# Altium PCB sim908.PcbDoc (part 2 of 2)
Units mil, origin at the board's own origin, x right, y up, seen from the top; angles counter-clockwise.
Board outline 6000 x 4000 mil, 2 copper layers (Top Layer, Bottom Layer); 77 components, 69 nets, 376 pads, 43 vias.
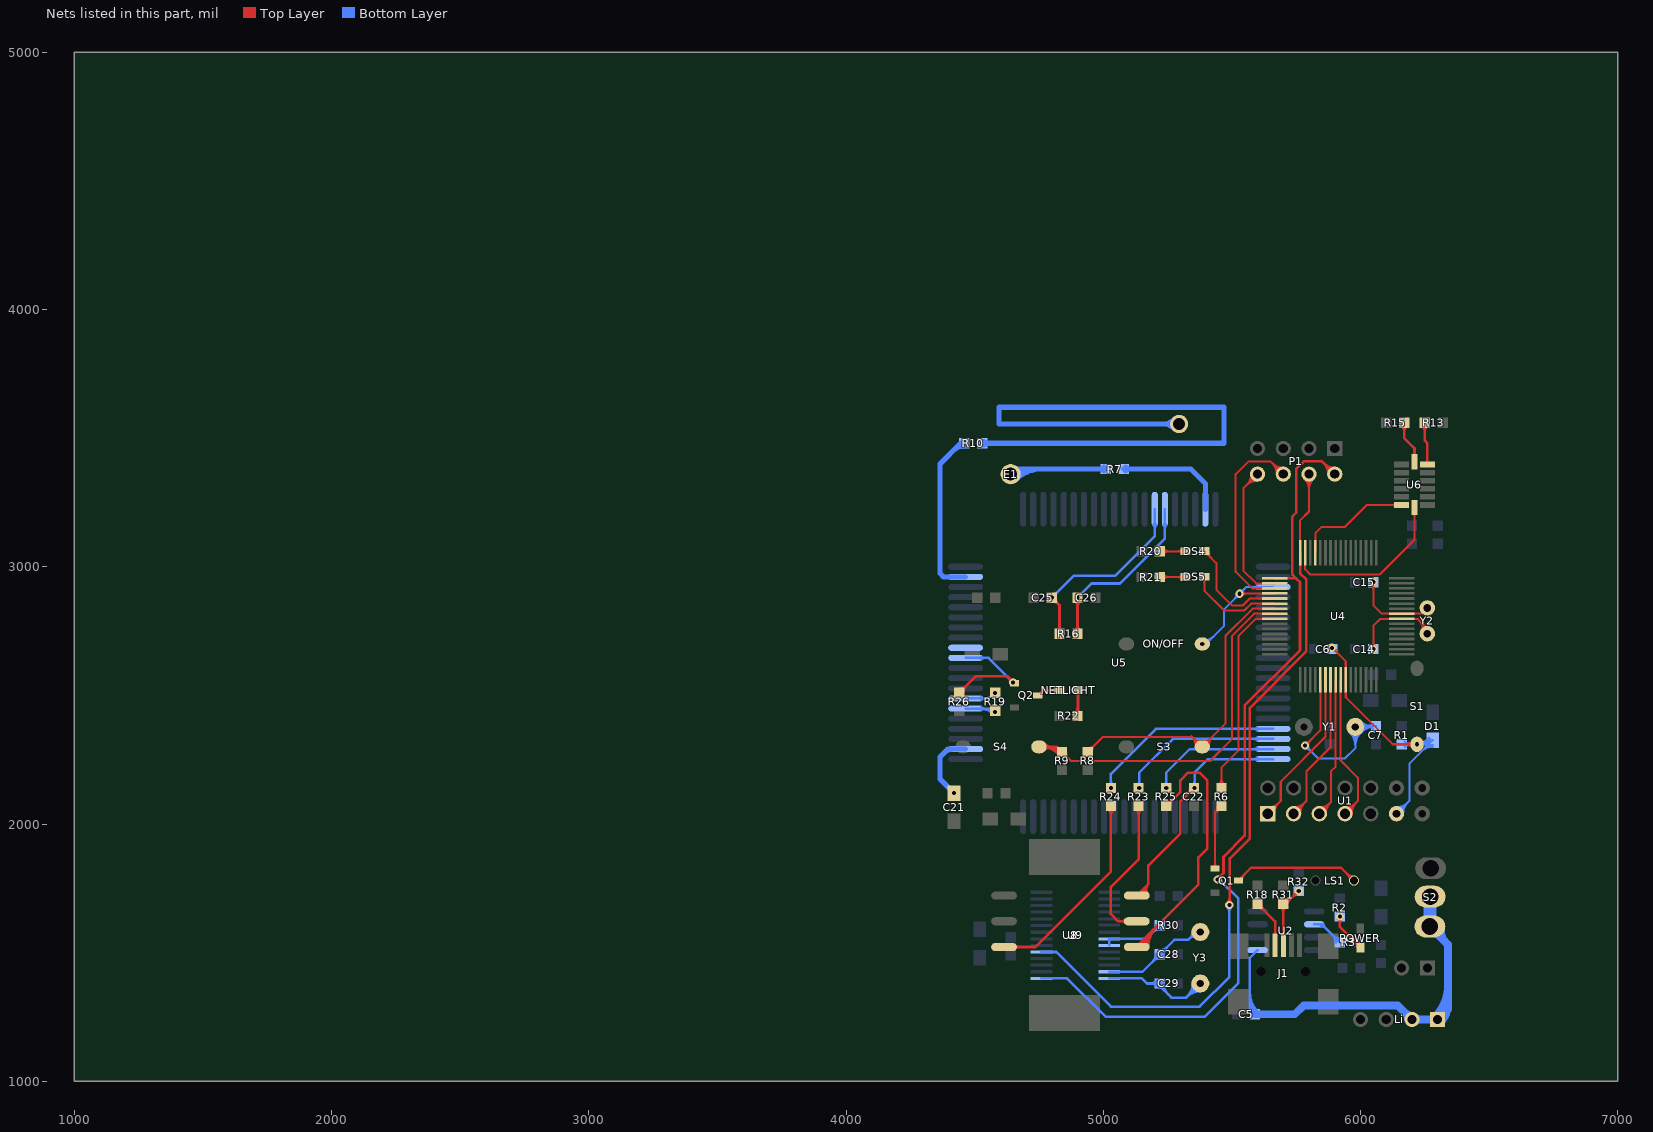
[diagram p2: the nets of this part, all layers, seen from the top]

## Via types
v1: diameter 31.5, hole 15.75, Top Layer to Bottom Layer, 41 vias
v2: diameter 39.37, hole 19.68, Top Layer to Bottom Layer, 2 vias

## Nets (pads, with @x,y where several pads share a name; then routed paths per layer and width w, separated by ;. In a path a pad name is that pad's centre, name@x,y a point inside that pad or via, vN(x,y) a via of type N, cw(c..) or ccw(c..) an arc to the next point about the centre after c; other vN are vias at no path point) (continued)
NetC7_2: C7.2 U4.53 Y1.1 | length 1325.3
  Top Layer w8: v1(5785,2305) 5844.25,2364.25 U4.53@5844.25,2560.79 ; v1@5785,2316.75 ccw(c5785,2345.11) 5805.06,2325.06 ccw(c5825.11,2305) v1@5796.75,2305
  Bottom Layer w8: v1@5785,2293.25 cw(c5785,2264.89) 5805.06,2284.94 cw(c5825.11,2305) v1@5796.75,2305 ; v1(5785,2305) 5835,2255 5940,2255 5979.92,2294.92 Y1.1@5979.92,2377.48 5982.44,2380 C7.2@6060,2380 ccw(c6060,2298.59) Y1.1@6002,2355.72 ; Y1.1@5958,2355.56 cw(c5905.08,2302.64) 5979.92,2302.64 cw(c6054.76,2302.64) Y1.1@6001.84,2355.56 ; Y1.1@5963.66,2361.22 cw(c5924.39,2321.95) 5979.92,2321.95 cw(c6035.45,2321.95) Y1.1@5996.18,2361.22 ; Y1.1@5969.31,2366.87 cw(c5943.71,2341.27) 5979.92,2341.27 cw(c6016.13,2341.27) Y1.1@5990.53,2366.87 ; Y1.1@5990.61,2366.95 cw(c6021.77,2336.25) 6021.77,2380 ; Y1.1@5996.18,2393.74 ccw(c6029.36,2426.92) 6029.36,2380 ; Y1.1@5996.31,2361.34 cw(c6040.89,2317.42) C7.2@6040.89,2380 ; Y1.1@6001.84,2399.4 ccw(c6048.68,2446.24) C7.2@6048.68,2380 ; C7.2@6048.69,2368.69 ccw(c6021.37,2341.37) 6021.37,2380 ccw(c6021.37,2418.63) C7.2@6048.69,2391.31
NetC14_2: C14.2 U4.8 Y2.2 | length 540.8
  Top Layer w8: v1@6041.69,2688.31 ccw(c6021.64,2708.36) 6050,2708.36 ccw(c6078.36,2708.36) v1@6058.31,2688.31 ; v1@6050,2685 6050,2770 6077.8,2797.8 U4.8@6160,2797.8 6222.2,2797.8 6260,2760 Y2.2@6260,2740 ; 6223.73,2796.27 cw(c6177.98,2750.53) Y2.2@6242.15,2742.29 ; 6235.24,2784.76 cw(c6198.39,2747.91) Y2.2@6250.08,2741.27 ; 6246.76,2773.24 cw(c6218.81,2745.29) Y2.2@6258.02,2740.25 ; 6249.76,2770.24 ccw(c6260,2780.49) Y2.2@6260,2766
  other v1: 6050,2680
NetC15_2: C15.2 U4.9 Y2.1 | length 367.4
  Top Layer w8: v1@6041.69,2931.69 cw(c6021.64,2911.64) 6050,2911.64 cw(c6078.36,2911.64) v1@6058.31,2931.69 ; v1(6050,2940) 6050,2849.96 6082.48,2817.48 U4.9@6160,2817.48 6237.48,2817.48 Y2.1@6260,2840
NetC25_1: C25.1 R16.2 U5.74 | length 976.7
  Top Layer w10: C25.1@4800,2865 cw(c4800,2828.79) 4825.61,2854.39 cw(c4851.21,2880) C25.1@4815,2880 ; C25.1@4800,2869.25 cw(c4800,2843.3) 4818.35,2861.65 cw(c4836.7,2880) C25.1@4810.75,2880 ; v1(4800,2880) 4830,2850 R16.2@4830,2740 ; R16.2@4819.39,2750.61 ccw(c4793.79,2776.21) 4830,2776.21 ccw(c4866.21,2776.21) R16.2@4840.61,2750.61
  Bottom Layer w10: v1(4800,2880) 4885,2965 5045.35,2965 5200.35,3120 U5.74@5200.35,3223.43 ; v1@4800,2890.75 ccw(c4800,2916.7) 4818.35,2898.35 ccw(c4836.7,2880) v1@4810.75,2880 ; U5.74@5195.54,3162.51 cw(c5183.91,3150.88) 5200.35,3150.88 cw(c5216.8,3150.88) U5.74@5205.17,3162.51
NetC26_1: C26.1 R16.1 U5.75 | length 909.5
  Top Layer w10: R16.1@4889.39,2750.61 ccw(c4863.79,2776.21) 4900,2776.21 ccw(c4936.21,2776.21) R16.1@4910.61,2750.61 ; C26.1@4889.39,2869.39 cw(c4863.79,2843.79) 4900,2843.79 cw(c4936.21,2843.79) C26.1@4910.61,2869.39 ; C26.1@4892.4,2872.4 cw(c4874.05,2854.05) 4900,2854.05 cw(c4925.95,2854.05) C26.1@4907.6,2872.4 ; R16.1@4900,2740 v1(4900,2880)
  Bottom Layer w10: v1(4900,2880) 4955,2935 5064.72,2935 5239.72,3110 U5.75@5239.72,3223.43 ; v1@4900,2890.75 ccw(c4900,2916.7) 4918.35,2898.35 ccw(c4936.7,2880) v1@4910.75,2880 ; U5.75@5234.91,3162.51 cw(c5223.28,3150.88) 5239.72,3150.88 cw(c5256.17,3150.88) U5.75@5244.54,3162.51
NetC28_1: C28.1 U9.27 Y3.2 | length 629.7
  Bottom Layer w10: U9.27@5023.78,1425.59 5152.26,1425.59 C28.1@5220,1493.33 5276.67,1550 5330,1550 5360.08,1580.08 Y3.2@5377.48,1580.08 ; C28.1@5205,1493.33 cw(c5168.79,1493.33) 5194.39,1467.73 cw(c5220,1442.12) C28.1@5220,1478.33 ; C28.1@5220,1508.33 ccw(c5220,1544.55) 5245.61,1518.94 ccw(c5271.21,1493.33) C28.1@5235,1493.33 ; 5332.52,1552.52 cw(c5358.58,1526.47) Y3.2@5370.83,1561.22 ; 5338.57,1558.57 ccw(c5317.07,1580.08) Y3.2@5347.48,1580.08 ; 5343.75,1563.75 cw(c5364.43,1543.07) Y3.2@5374.15,1570.65
NetC29_1: C29.1 U9.28 Y3.1 | length 755.3
  Bottom Layer w10: U9.28@5023.78,1400 5150,1400 5170,1380 C29.1@5220,1380 ; C29.1@5209.39,1369.39 ccw(c5183.79,1343.79) 5183.79,1380 ccw(c5183.79,1416.21) C29.1@5209.39,1390.61 ; C29.1@5220,1365 cw(c5220,1352.93) C29.1@5228.54,1361.46 ; C29.1@5220,1390 C29.1@5220,1380 ; C29.1@5225,1380 ccw(c5261.21,1380) 5235.61,1354.39 ; C29.1@5235,1380 ccw(c5295.36,1380) 5252.68,1337.32 ; Y3.1@5347.48,1380.08 cw(c5275.05,1380.08) 5326.27,1328.87 cw(c5377.48,1277.65) Y3.1@5377.48,1350.08 ; Y3.1@5357.48,1380.08 cw(c5309.2,1380.08) 5343.34,1345.94 cw(c5377.48,1311.79) Y3.1@5377.48,1360.08 ; Y3.1@5377.48,1380.08 5322.4,1325 5265,1325 5220,1370 C29.1@5220,1380
NetDS1_2: POWER.2 R2.1 | length 231.8
  Top Layer w10: v1@5912.4,1632.4 cw(c5894.05,1614.05) 5920,1614.05 cw(c5945.95,1614.05) v1@5927.6,1632.4 ; v1(5920,1640) 5920,1600 POWER.2@6000,1520 ; 5974.39,1545.61 ccw(c6000,1571.21) POWER.2@6000,1535 ; POWER.2@5986.46,1533.54 cw(c5977.93,1525) POWER.2@5990,1525
NetDS4_2: DS4.2 R20.1 | length 202.4
  Top Layer w8: R20.1@5220,3060 DS4.2@5320,3060 ; R20.1@5231.31,3048.69 cw(c5258.63,3021.37) 5258.63,3060 cw(c5258.63,3098.63) R20.1@5231.31,3071.31 ; DS4.2@5307.22,3052.22 ccw(c5288.44,3033.44) 5288.44,3060 ccw(c5288.44,3086.56) DS4.2@5307.22,3067.78
NetDS5_2: DS5.2 R21.1 | length 202.4
  Top Layer w8: R21.1@5220,2960 DS5.2@5320,2960 ; R21.1@5231.31,2948.69 cw(c5258.63,2921.37) 5258.63,2960 cw(c5258.63,2998.63) R21.1@5231.31,2971.31 ; DS5.2@5307.22,2952.22 ccw(c5288.44,2933.44) 5288.44,2960 ccw(c5288.44,2986.56) DS5.2@5307.22,2967.78
NetDS6_1: NETLIGHT.1 R22.1 | length 196.6
  Top Layer w10: R22.1@4889.39,2430.61 ccw(c4859.13,2460.87) 4901.93,2460.87 ; NETLIGHT.1@4894.86,2513.93 cw(c4877.79,2496.86) 4901.93,2496.86 cw(c4926.07,2496.86) NETLIGHT.1@4909,2513.93 ; R22.1@4900,2420 4901.93,2421.93 NETLIGHT.1@4901.93,2521 ; 4901.93,2451.56 ccw(c4931.56,2451.56) R22.1@4910.61,2430.61
NetDS6_2: NETLIGHT.2 Q2.3 | length 151.4
  Top Layer w10: Q2.3@4745.28,2500 4765.27,2520 ; Q2.3@4757.98,2500.48 cw(c4783.04,2502.23) 4765.27,2520 ; NETLIGHT.2@4816.93,2512.93 ccw(c4799.86,2495.86) 4799.86,2520 ccw(c4799.86,2544.14) NETLIGHT.2@4816.93,2527.07 ; NETLIGHT.2@4829,2520 4765.27,2520
NetE1_1: E1.1 R7.2 | length 596.9
  Bottom Layer w20: E1.1@4640,3360 4660,3380 R7.2@5010,3380 ; E1.1@4646.63,3353.37 cw(c4710.91,3289.09) 4710.91,3380 ; E1.1@4660.77,3339.23 cw(c4759.19,3240.81) 4759.19,3380 ; R7.2@5002.93,3372.93 ccw(c4985.86,3355.86) 4985.86,3380 ccw(c4985.86,3404.14) R7.2@5002.93,3387.07
NetE2_1: pad.1 R10.2 | length 2854.4
  Bottom Layer w20: R10.2@4530,3480 5470,3480 5470,3620 4595,3620 4595,3555 pad.1@5295,3555 ; R10.2@4537.07,3472.93 cw(c4554.14,3455.86) 4554.14,3480 cw(c4554.14,3504.14) R10.2@4537.07,3487.07 ; pad.1@5277.02,3537.02 ccw(c5233.6,3493.6) 5233.6,3555 ccw(c5233.6,3616.4) pad.1@5277.02,3572.98
NetJ1_2: J1.2 R18.2 | length 264.6
  Top Layer w10: R18.2@5600,1675 cw(c5600,1638.79) 5625.61,1664.39 cw(c5651.21,1690) R18.2@5615,1690 ; R18.2@5600,1690 5668.5,1621.5 J1.2@5668.5,1529.06 ; J1.2@5665.08,1567.91 ccw(c5656.81,1576.18) 5668.5,1576.18 ccw(c5680.19,1576.18) J1.2@5671.93,1567.91
NetJ1_3: J1.3 R31.2 R32.1 | length 443
  Top Layer w10: R31.2@5689.39,1679.39 cw(c5663.79,1653.79) 5700,1653.79 cw(c5736.22,1653.78) R31.2@5710.61,1679.39 ; J1.3@5696.57,1567.91 ccw(c5688.31,1576.18) 5700,1576.18 ccw(c5711.69,1576.18) J1.3@5703.42,1567.91 ; J1.3@5700,1529.06 R31.2@5700,1690 5710,1690 v1(5760,1740) ; R31.2@5700,1695 ccw(c5700,1731.21) 5725.61,1705.61 ; R31.2@5700,1705 ccw(c5700,1765.36) 5742.68,1722.68 ; R31.2@5715,1690 cw(c5727.07,1690) R31.2@5718.54,1698.54 ; v1@5749.25,1740 cw(c5723.3,1740) 5741.65,1721.65 cw(c5760,1703.3) v1@5760,1729.25
NETLIGHT: Q2.1 R26.2 U5.51 | length 666
  Top Layer w10: R26.2@4440,2510 4505,2575 4626.97,2575 Q2.1@4654.72,2547.24 ; R26.2@4440,2525 ccw(c4440,2561.21) 4465.61,2535.61 ccw(c4491.21,2510) R26.2@4455,2510 ; 4630.26,2571.71 cw(c4608.55,2550) Q2.1@4639.25,2550 ; 4633.02,2568.95 cw(c4611.31,2547.24) Q2.1@4642.01,2547.24 ; 4635.01,2566.96 ccw(c4650,2581.94) v1@4650,2560.75
  Bottom Layer w10: U5.51@4465.12,2645.67 4554.33,2645.67 v1(4650,2550) ; U5.51@4526.04,2640.85 cw(c4537.66,2629.23) 4537.66,2645.67 cw(c4537.66,2662.11) U5.51@4526.04,2650.49 ; v1@4639.25,2550 ccw(c4613.3,2550) 4631.65,2568.35 ccw(c4650,2586.7) v1@4650,2560.75
NetLS1_2: LS1.2 Q1.3 | length 570.9
  Top Layer w10: Q1.3@5525.28,1780 5575.18,1829.9 5925.1,1829.9 LS1.2@5975,1780 ; Q1.3@5537.99,1780 cw(c5568.69,1780) 5546.98,1801.71 ; 5949.6,1805.41 cw(c5924.19,1780) LS1.2@5960.12,1780 ; 5950.07,1804.93 ccw(c5974.8,1829.66) LS1.2@5974.8,1794.68
NetQ1_1: Q1.1 R6.1 | length 336.6
  Top Layer w8: Q1.1@5429.2,1832.77 ccw(c5415.87,1846.1) 5434.72,1846.1 ccw(c5453.58,1846.1) Q1.1@5440.25,1832.77 ; Q1.1@5434.72,1827.24 5434.72,1880 5434.72,2044.72 R6.1@5460,2070 ; R6.1@5444.03,2069.1 cw(c5412.15,2067.3) 5434.73,2044.73 cw(c5457.3,2022.15) R6.1@5459.1,2054.03
NetR3_1: R3.1 U2.2 | length 212.4
  Bottom Layer w10: U2.2@5820,1610 5850,1610 R3.1@5920,1540 ; U2.2@5848,1603 cw(c5848,1581.27) 5863.36,1596.64 ; U2.2@5855,1610 ccw(c5867.07,1610) 5858.54,1601.46 ; R3.1@5905,1540 ccw(c5868.79,1540) 5894.39,1565.61 ccw(c5920,1591.21) R3.1@5920,1555
NetR7_1: R7.1 U5.79 | length 478.2
  Bottom Layer w20: R7.1@5080,3380 5340,3380 5397.2,3322.8 U5.79@5397.2,3223.43 ; R7.1@5087.07,3372.93 cw(c5104.14,3355.86) 5104.14,3380 cw(c5104.14,3404.14) R7.1@5087.07,3387.07
NetR10_1: R10.1 U5.59 | length 706.6
  Bottom Layer w20: 4417.32,3452.32 cw(c4460,3409.64) R10.1@4460,3470 ; R10.1@4460,3480 4445,3480 4365,3400 4365,2975 4379.37,2960.63 U5.59@4465.12,2960.63
NetR13_2: R13.2 U6.6 | length 245.6
  Top Layer w10: R13.2@6239.39,3549.39 cw(c6213.79,3523.79) 6250,3523.79 cw(c6286.21,3523.79) R13.2@6260.61,3549.39 ; R13.2@6250,3560 6250,3490 6260,3480 U6.6@6260,3397.5 ; U6.6@6255.88,3401.62 ccw(c6245.93,3411.57) 6260,3411.57 ccw(c6274.07,3411.57) U6.6@6264.12,3401.62
NetR15_2: R15.2 U6.7 | length 247.5
  Top Layer w10: R15.2@6159.39,3549.39 cw(c6133.79,3523.79) 6170,3523.79 cw(c6206.21,3523.79) R15.2@6180.61,3549.39 ; R15.2@6170,3560 6170,3500 6210,3460 U6.7@6210,3408 ; U6.7@6205.88,3430.82 ccw(c6195.93,3440.77) 6210,3440.77 ccw(c6224.07,3440.77) U6.7@6214.12,3430.82
NetR17_1: 
NetR19_1: R19.1 U5.46 | length 261.9
  Bottom Layer w10: U5.46@4465.12,2448.82 4566.18,2448.82 v1(4580,2435) ; U5.46@4520.69,2448.82 cw(c4520.69,2375.69) v1@4572.4,2427.4 ; U5.46@4526.04,2444 cw(c4537.66,2432.38) 4537.66,2448.82 cw(c4537.66,2465.26) U5.46@4526.04,2453.64 ; 4544.83,2448.82 cw(c4544.83,2399.83) v1@4579.47,2434.47 ; 4568.97,2448.82 cw(c4568.97,2423.97) v1@4586.54,2441.54
NetR19_2: R19.2 U5.47 | length 185.5
  Bottom Layer w10: U5.47@4465.12,2488.19 4553.19,2488.19 v1@4575,2510 ; U5.47@4526.04,2483.37 cw(c4537.66,2471.75) 4537.66,2488.19 cw(c4537.66,2504.63) U5.47@4526.04,2493.01 ; 4553.12,2488.12 cw(c4580,2461.23) v1@4580,2499.25 ; 4565.19,2500.19 ccw(c4555.38,2510) v1@4569.25,2510
  other v1: 4580,2510
NetR29_1: 
NetR30_2: R30.2 U9.22 U9.23 | length 300.7
  Bottom Layer w10: U9.23@5023.78,1527.95 U9.22@5023.78,1553.54 5166.88,1553.54 R30.2@5220,1606.67 ; R30.2@5205,1606.67 cw(c5168.79,1606.67) 5194.39,1581.06 cw(c5220,1555.45) R30.2@5220,1591.67
P4.0: ON/OFF.2 U4.36 U5.3 | length 813.9
  Top Layer w8: v1@5531.22,2896.22 U4.36@5666.3,2896.22 ; v1@5538.31,2886.69 cw(c5561.31,2863.69) 5561.31,2896.22 ; v1@5538.31,2903.31 ccw(c5555.42,2920.42) 5555.42,2896.22
  Bottom Layer w8: v1@5385,2695.75 ccw(c5385,2721.7) 5403.35,2703.35 ; v1(5385,2700) 5390,2695 5395,2695 5470,2770 5470,2835 5556.26,2921.26 U5.3@5660,2921.26 ; v1@5385,2703.75 ccw(c5385,2749.01) 5417,2717 ; v1@5385,2711.75 ccw(c5385,2776.32) 5430.66,2730.66 ; v1@5518.25,2895 cw(c5489.89,2895) 5509.94,2874.94 cw(c5530,2854.89) v1@5530,2883.25 ; v1@5530,2906.75 ccw(c5530,2935.11) 5550.06,2915.06 ccw(c5570.11,2895) v1@5541.75,2895 ; U5.3@5598.37,2915.74 ccw(c5585.04,2902.4) 5585.04,2921.26 ccw(c5585.04,2940.12) U5.3@5598.37,2926.78
  other v1: 5530,2895
P4.1: DS4.1 U4.37 | length 489.5
  Top Layer w8: DS4.1@5392.93,3061 5440,3013.93 5440,2910 5500,2850 5543.18,2850 5569.71,2876.53 U4.37@5666.3,2876.53 ; DS4.1@5397.93,3050 cw(c5397.93,3035.51) 5408.17,3045.76 ; DS4.1@5400.93,3061 ccw(c5420.24,3061) DS4.1@5406.58,3047.34 ; DS4.1@5408.93,3061 ccw(c5447.56,3061) 5420.24,3033.69
P4.2: DS5.1 U4.38 | length 412.1
  Top Layer w8: DS5.1@5385.15,2953.22 cw(c5366.37,2934.44) 5392.93,2934.44 cw(c5419.48,2934.44) DS5.1@5400.71,2953.22 ; DS5.1@5392.93,2961 5392.93,2907.07 5470,2830 5548.63,2830 5575.48,2856.85 U4.38@5666.3,2856.85
P4.3: R8.1 S3.1 U4.39 | length 1469.5
  Top Layer w8: R8.1@4940,2280 4999,2339 5346,2339 S3.1@5385,2300 5475,2390 5475,2730.91 5581.25,2837.16 U4.39@5666.3,2837.16 ; R8.1@4940,2296 ccw(c4940,2334.63) 4967.31,2307.31 ccw(c4994.63,2280) R8.1@4956,2280 ; 5343.5,2341.5 cw(c5305.85,2303.84) S3.1@5359.03,2301.09 ; 5352.69,2332.31 ccw(c5380,2359.63) S3.1@5380,2321 ; 5356.22,2328.78 cw(c5330.02,2302.59) S3.1@5367.02,2300.67 ; S3.1@5390,2321 ccw(c5390,2359.63) 5417.31,2332.31 ; S3.1@5403,2300 cw(c5446.46,2300) 5415.73,2330.73 ; S3.1@5411,2300 cw(c5473.77,2300) 5429.38,2344.38
P4.4: R9.1 S4.1 U4.40 | length 1736.6
  Top Layer w8: R9.1@4840,2264 cw(c4840,2225.37) 4867.31,2252.69 cw(c4894.63,2280) R9.1@4856,2280 ; R9.1@4840,2280 4875,2245 5415,2245 5500,2330 5500,2730.46 5587.02,2817.48 U4.40@5666.3,2817.48
  Top Layer w10: S4.1@4750,2300 4820,2300 R9.1@4840,2280 ; S4.1@4755.5,2300 cw(c4755.5,2195.5) R9.1@4829.39,2269.39 ; S4.1@4769.14,2285.86 cw(c4803.28,2251.72) 4803.28,2300 cw(c4803.28,2348.28) S4.1@4769.14,2314.14 ; S4.1@4779.64,2300 cw(c4779.64,2219.64) R9.1@4836.46,2276.46 ; 4803.79,2300 cw(c4803.79,2243.79) R9.1@4843.54,2283.54
P4.5: R6.2 U4.41 | length 847
  Top Layer w8: R6.2@5448.69,2151.31 ccw(c5421.37,2178.63) 5460,2178.63 ccw(c5498.63,2178.63) R6.2@5471.31,2151.31 ; R6.2@5460,2140 5460,2220 5525,2285 5525,2730 5592.8,2797.8 U4.41@5666.3,2797.8
POWER: C5.2 Li.1 Li.2 S2.1 S2.2 U2.5 | length 2255.5
  Bottom Layer w10: 5570,1296.21 ccw(c5626.21,1296.21) C5.2@5586.46,1256.46 ; 5570,1320.36 ccw(c5650.36,1320.36) C5.2@5593.54,1263.54 ; 5570,1344.5 ccw(c5674.5,1344.5) C5.2@5600.61,1270.61 ; C5.2@5590,1260 5570,1280 5570,1480 U2.5@5600,1510
  Bottom Layer w30: C5.2@5590,1260 5745,1260 5779.53,1294.53 6145.47,1294.53 Li.2@6200,1240 6270,1240 ; Li.2@6185.47,1240 ccw(c6150.4,1240) 6175.2,1264.8 ccw(c6200,1289.6) Li.2@6200,1254.53 ; Li.2@6210.27,1229.73 cw(c6235.07,1204.93) 6235.07,1240 cw(c6235.07,1275.07) Li.2@6210.27,1250.27 ; S2.1@6269.84,1601.54 6340,1531.38 6340,1480 ; Li.1@6289.73,1229.73 ccw(c6264.93,1204.93) 6264.93,1240 ccw(c6264.93,1275.07) 6289.73,1250.27 ccw(c6168.36,1371.64) 6340,1371.64 ; Li.1@6300,1240 6340,1280 6340,1480 ; Li.1@6300,1254.53 ccw(c6300,1289.6) 6324.8,1264.8 ccw(c6349.6,1240) Li.1@6314.53,1240 ; Li.1@6310.94,1229.06 ccw(c6240.79,1299.21) 6340,1299.21 ; S2.1@6314.31,1596.13 ccw(c6375.07,1583.95) 6331.25,1540.13 ; 6340,1505 6340,1480
  Bottom Layer w50: S2.1@6257.47,1613.91 ccw(c6225.22,1646.16) 6270.83,1646.16 ; S2.1@6269.84,1601.54 6270.83,1602.52 S2.2@6270.83,1717.68
RST: C6.2 D1.A R1.1 S1.1 U1.11 U4.58 | length 1861.1
  Top Layer w8: v1@5890,2673.25 cw(c5890,2644.89) 5910.06,2664.94 cw(c5930.11,2685) v1@5901.75,2685 ; v1(5890,2685) 5942.68,2632.32 U4.58@5942.68,2560.79 ; U4.58@5943.36,2560.1 U4.58@5942.68,2560.79 ; S1.1@6205.15,2295.15 ccw(c6169.3,2259.3) 6169.3,2310 ccw(c6169.3,2360.7) S1.1@6205.15,2324.85 ; S1.1@6210.81,2300.81 ccw(c6188.62,2278.62) 6188.62,2310 ccw(c6188.62,2341.38) S1.1@6210.81,2319.19 ; S1.1@6211.69,2301.69 ccw(c6191.64,2281.64) 6191.64,2310 ccw(c6191.64,2338.36) S1.1@6211.69,2318.31 ; v1(6220,2310) 6125,2310 5942.68,2492.32 U4.58@5942.68,2560.79
  Bottom Layer w8: U1.11@6140,2040 6190,2090 6190,2234.94 D1.A@6281,2325.94 6265.06,2310 R1.1@6160,2310 ; U1.11@6140,2058 ccw(c6140,2101.46) 6170.73,2070.73 ccw(c6201.46,2040) U1.11@6158,2040 ; U1.11@6140,2066 ccw(c6140,2128.77) 6184.38,2084.38 ccw(c6228.77,2040) U1.11@6166,2040 ; R1.1@6171.31,2298.69 cw(c6198.63,2271.37) 6198.63,2310 cw(c6198.63,2348.63) R1.1@6171.31,2321.31 ; 6203.9,2310 ccw(c6203.9,2398.04) D1.A@6266.15,2335.79 ; v1@6211.69,2301.69 ccw(c6191.64,2281.64) 6191.64,2310 ccw(c6191.64,2338.36) v1@6211.69,2318.31 ; v1@6223.21,2310 ccw(c6223.21,2378.73) D1.A@6271.81,2330.13 ; v1@6228.31,2301.69 cw(c6248.36,2281.64) 6248.36,2310 cw(c6248.36,2338.36) v1@6228.31,2318.31 ; 6236.62,2281.55 cw(c6281,2237.17) D1.A@6281,2299.94 ; 6242.52,2310 ccw(c6242.52,2359.41) D1.A@6277.46,2324.47 ; 6248.69,2293.62 ccw(c6221.37,2320.94) D1.A@6260,2320.94 ; 6250.27,2295.21 cw(c6281,2264.48) D1.A@6281,2307.94 ; D1.A@6256.71,2310 cw(c6256.71,2296.64) D1.A@6266.15,2306.09
SCL: U4.31 U6.14 | length 708
  Top Layer w8: U4.31@5785.2,3054.49 5785.2,2989.8 5805,2970 6075,2970 6127.5,3022.5 ; 6130,3025 6127.5,3022.5 ; U6.14@6205.17,3206.47 cw(c6193.52,3194.82) 6210,3194.82 cw(c6226.48,3194.82) U6.14@6214.83,3206.47 ; U6.14@6210,3230 6210,3105 6127.5,3022.5
SDA: U4.29 U6.13 | length 486.1
  Top Layer w8: U4.29@5824.57,3054.49 5824.57,3129.57 5850,3155 5940,3155 6025,3240 6075,3240 ; 6079.5,3240 6075,3240 ; U6.13@6135.97,3235.17 ccw(c6124.32,3223.52) 6124.32,3240 ccw(c6124.32,3256.48) U6.13@6135.97,3244.83 ; U6.13@6159.5,3240 6075,3240
SIM_CLK: R25.1 U5.19 | length 579.4
  Bottom Layer w10: v1@5237.4,2147.6 ccw(c5219.05,2165.95) 5245,2165.95 ccw(c5270.95,2165.95) v1@5252.6,2147.6 ; v1(5245,2140) 5245,2200 5336.34,2291.34 U5.19@5660,2291.34 ; U5.19@5599.08,2286.52 ccw(c5587.45,2274.9) 5587.45,2291.34 ccw(c5587.45,2307.78) U5.19@5599.08,2296.15
SIM_CLK_CN: R25.2 U8.3 | length 1343.4
  Top Layer w10: U8.3@5130.46,1521.78 5130.46,1525.46 5370,1765 5370,1870 5405,1905 5405,2170 5375,2200 5330,2200 5300,2170 5300,2125 R25.2@5245,2070 ; U8.3@5135.46,1521.78 cw(c5156.43,1521.78) U8.3@5141.6,1536.6 ; U8.3@5145.46,1521.78 cw(c5190.57,1521.78) 5158.67,1553.67 ; U8.3@5155.46,1521.78 cw(c5224.71,1521.78) 5175.74,1570.74 ; U8.3@5165.46,1521.78 cw(c5258.85,1521.78) 5192.82,1587.82 ; U8.3@5175.46,1521.78 cw(c5293,1521.78) 5209.89,1604.89 ; R25.2@5245,2085 ccw(c5245,2121.21) 5270.61,2095.61 ccw(c5296.21,2070) R25.2@5260,2070
SIM_DATA: R24.2 U5.17 | length 824.1
  Bottom Layer w10: v1@5022.4,2147.6 ccw(c5004.05,2165.95) 5030,2165.95 ccw(c5055.95,2165.95) v1@5037.6,2147.6 ; v1(5030,2140) 5030,2195 5205.08,2370.08 U5.17@5660,2370.08 ; U5.17@5599.08,2365.26 ccw(c5587.45,2353.64) 5587.45,2370.08 ccw(c5587.45,2386.52) U5.17@5599.08,2374.89
SIM_DATA_CN: R24.1 U8.6 | length 900.3
  Top Layer w10: U8.6@4614.4,1521.78 4736.78,1521.78 4847.5,1632.5 ; U8.6@4656.25,1514.18 cw(c4674.6,1495.83) 4674.6,1521.78 cw(c4674.6,1547.73) U8.6@4656.25,1529.38 ; 4840,1625 4847.5,1632.5 ; R24.1@5019.39,2059.39 cw(c4993.79,2033.79) 5030,2033.79 cw(c5066.21,2033.79) R24.1@5040.61,2059.39 ; R24.1@5030,2070 5030,1815 4847.5,1632.5
SIM_RST: R23.1 U5.18 | length 700.7
  Bottom Layer w10: v1@5132.4,2147.6 ccw(c5114.05,2165.95) 5140,2165.95 ccw(c5165.95,2165.95) v1@5147.6,2147.6 ; v1(5140,2140) 5140,2200 5270.71,2330.71 U5.18@5660,2330.71 ; U5.18@5599.08,2325.89 ccw(c5587.45,2314.27) 5587.45,2330.71 ccw(c5587.45,2347.15) U5.18@5599.08,2335.52
SIM_RST_CN: R23.2 U8.2 | length 674.3
  Top Layer w10: U8.2@5088.61,1614.18 ccw(c5070.26,1595.83) 5070.26,1621.78 ccw(c5070.26,1647.73) U8.2@5088.61,1629.38 ; R23.2@5126.89,2059.39 cw(c5101.29,2033.79) 5137.5,2033.79 cw(c5173.71,2033.79) R23.2@5148.11,2059.39 ; U8.2@5130.46,1621.78 5058.22,1621.78 5030,1650 5030,1755 5137.5,1862.5 R23.2@5137.5,2070
SIM_VDD: C22.2 U5.20 U8.1 | length 1217.2
  Top Layer w10: U8.1@5130.46,1721.78 5175.46,1766.78 ; U8.1@5149.57,1709.89 cw(c5169.15,1725.26) 5151.55,1742.86 ; U8.1@5157.44,1716.06 cw(c5178.08,1732.28) 5159.52,1750.83 ; U8.1@5165.3,1722.24 cw(c5187.01,1739.29) 5167.49,1758.81 ; U8.1@5173.17,1728.42 cw(c5195.93,1746.3) 5175.46,1766.78 ; 5332.38,2119.88 cw(c5355,2097.27) C22.2@5355,2129.25 ; C22.2@5337.5,2140 cw(c5301.29,2140) 5326.89,2114.39 cw(c5352.5,2088.79) C22.2@5352.5,2125 ; C22.2@5338.42,2125.92 ccw(c5324.34,2140) C22.2@5344.25,2140 ; C22.2@5352.5,2140 5300,2087.5 5300,1963.28 5175.46,1838.75 5175.46,1766.78
  Bottom Layer w10: v1@5347.4,2147.6 ccw(c5329.05,2165.95) 5355,2165.95 ccw(c5380.95,2165.95) v1@5362.6,2147.6 ; v1(5355,2140) 5355,2200 5406.97,2251.97 U5.20@5660,2251.97 ; U5.20@5599.08,2247.15 ccw(c5587.45,2235.53) 5587.45,2251.97 ccw(c5587.45,2268.41) U5.20@5599.08,2256.78
STATUS: U5.52
TCK: U1.7 U4.57 | length 736.1
  Top Layer w8: U4.57@5922.99,2560.79 5922.99,2482.01 5922.99,2247.01 5990,2180 5990,2090 U1.7@5940,2040 ; U1.7@5940,2058 ccw(c5940,2101.46) 5970.73,2070.73 ccw(c6001.46,2040) U1.7@5958,2040 ; U1.7@5940,2066 ccw(c5940,2128.77) 5984.39,2084.38 ccw(c6028.77,2040) U1.7@5966,2040
TDI: U1.3 U4.55 | length 747.1
  Top Layer w8: U1.3@5740,2040 5790.23,2090.23 5790.23,2204.77 5883.62,2298.17 U4.55@5883.62,2560.79 ; U1.3@5740,2058 ccw(c5740,2101.46) 5770.73,2070.73 ccw(c5801.46,2040) U1.3@5758,2040 ; U1.3@5740,2066 ccw(c5740,2128.77) 5784.39,2084.38 ccw(c5828.77,2040) U1.3@5766,2040
TDO: U1.1 U4.54 | length 780.4
  Top Layer w8: U1.1@5640,2040 5690,2090 5690,2165 5863.94,2338.94 U4.54@5863.94,2560.79 ; U1.1@5640,2058 ccw(c5640,2101.46) 5670.73,2070.73 ccw(c5701.46,2040) U1.1@5658,2040 ; U1.1@5640,2066 ccw(c5640,2128.77) 5684.39,2084.38 ccw(c5728.77,2040) U1.1@5666,2040
TMS: U1.5 U4.56 | length 713.9
  Top Layer w8: U1.5@5840,2040 5885,2085 5885,2205 5903.31,2223.31 5903.31,2292.4 U4.56@5903.31,2560.79 ; U1.5@5840,2058 ccw(c5840,2101.46) 5870.73,2070.73 ccw(c5901.46,2040) U1.5@5858,2040 ; U1.5@5840,2066 ccw(c5840,2128.77) 5884.39,2084.38 ccw(c5928.77,2040) U1.5@5866,2040
URXD0: P1.2 U4.33 U9.1 | length 3562.9
  Top Layer w8: U4.33@5666.3,2955.28 5749.73,2955.28
  Top Layer w10: v1@5444.11,1785.89 5467.44,1809.22 5467.44,1872.44 5550,1955 5550,2460 5765,2675 5765,2940 5749.73,2955.28 5735,2970 5735,3195 5750,3210 5750,3380 5780,3410 5850,3410 P1.2@5900,3360 ; v1@5445,1795.75 ccw(c5445,1817.4) 5460.31,1802.09 ; v1@5455.75,1785 cw(c5485.99,1785) 5464.61,1806.39 ; P1.2@5875.47,3360 ccw(c5816.26,3360) 5858.13,3401.87 ccw(c5900,3443.74) P1.2@5900,3384.53 ; P1.2@5885.47,3360 ccw(c5850.4,3360) 5875.2,3384.8 ccw(c5900,3409.6) P1.2@5900,3374.53
  Bottom Layer w10: U9.1@4760,1400 4860,1400 5010,1250 5393.28,1250 5525,1381.72 5525,1710 5450,1785 v1(5445,1785) ; v1@5445,1774.25 cw(c5445,1736.23) 5471.88,1763.12 ; v1@5455.75,1785 ccw(c5469.62,1785) 5459.81,1775.19
URXD1: P1.6 U4.35 | length 947.5
  Top Layer w8: U4.35@5666.3,2915.91 5579.1,2915.91 5515,2980 5515,3360 5565,3410 5650,3410 P1.6@5700,3360 ; P1.6@5674.47,3360 ccw(c5612.84,3360) 5656.42,3403.58 ccw(c5700,3447.16) P1.6@5700,3385.53 ; P1.6@5682.47,3360 ccw(c5640.16,3360) 5670.08,3389.92 ccw(c5700,3419.84) P1.6@5700,3377.53
UTXD0: P1.4 U4.32 U9.5 | length 3262.5
  Top Layer w8: U4.32@5765.51,3054.49 5765.51,3180.51 5800,3215 P1.4@5800,3360 ; P1.4@5781.95,3341.95 cw(c5738.37,3298.37) 5800,3298.37 cw(c5861.63,3298.37) P1.4@5818.05,3341.95 ; P1.4@5787.61,3347.61 cw(c5757.68,3317.68) 5800,3317.68 cw(c5842.32,3317.68) P1.4@5812.39,3347.61
  Top Layer w10: v1@5482.4,1692.6 ccw(c5457.87,1717.13) 5492.56,1717.13 ; v1@5492.56,1682.56 5492.56,1866.06 5570,1943.5 5570,2451.72 5790,2671.72 5790,2950 ; 5492.56,1704.77 ccw(c5509.77,1704.77) v1@5497.6,1692.6 ; U4.32@5765.51,3054.49 5765.51,2974.49 5790,2950 ; 5790,2905 5790,2950
  Bottom Layer w10: U9.5@4760,1502.36 4817.64,1502.36 5030,1290 5375,1290 5490,1405 5490,1680 v1@5495,1685 ; v1@5482.4,1677.4 cw(c5464.05,1659.05) 5490,1659.05 cw(c5515.95,1659.05) v1@5497.6,1677.4
  other v1: 5490,1685
UTXD1: P1.8 U4.34 | length 702.8
  Top Layer w8: P1.8@5574.47,3360 cw(c5512.84,3360) 5556.42,3316.42 cw(c5600,3272.84) P1.8@5600,3334.47 ; P1.8@5582.47,3360 cw(c5540.16,3360) 5570.08,3330.08 cw(c5600,3300.16) P1.8@5600,3342.47 ; P1.8@5600,3360 5545,3305 5545,2985 5594.41,2935.59 U4.34@5666.3,2935.59
VRTC: C21.1 U5.42 | length 303.4
  Bottom Layer w20: 4384.28,2279.28 cw(c4409.02,2254.55) U5.42@4409.02,2289.53 ; v1(4420,2120) 4365,2175 4365,2260 4396.34,2291.34 U5.42@4465.12,2291.34
pads on no net: J1.4 J1.MH1 J1.MH2 U1.4 U1.6 U1.8 U1.10 U1.12 U1.13 U1.14 U4.2 U4.3 U4.4 U4.5 U4.6 U4.7 U4.10 U4.11 U4.12 U4.15 U4.16 U4.17 U4.18 U4.19 U4.20 U4.21 U4.22 U4.23 U4.24 U4.25 U4.26 U4.27 U4.28 U4.30 U4.42 U4.43 U4.44 U4.45 U4.46 U4.47 U4.48 U4.49 U4.50 U4.51 U4.59 U4.60 U4.61 U5.4 U5.6 U5.7 U5.8 U5.9 U5.11 U5.12 U5.13 U5.21 U5.22 U5.23 U5.24 U5.25 U5.26 U5.27 U5.28 U5.29 U5.30 U5.31 U5.32 U5.33 U5.34 U5.35 U5.36 U5.44 U5.45 U5.48 U5.49 U5.50 U5.53 U5.54 U5.55 U5.56 U5.66 U5.67 U5.69 U5.70 U5.72 U5.73 U5.76 U6.3 U6.10 U6.11 U8. U8.5 U9.2 U9.3 U9.6 U9.9 U9.10 U9.11 U9.12 U9.13 U9.14

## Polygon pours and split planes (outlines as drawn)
GND on Top Layer "Top Layer-No Net" (hatched 90Degree grid 11.81 track 11.81, remove dead copper, pour order 1000): 4295,3090 5530,3090 5545,3075 5535,3085 5535,3685 6385,3685 6415,3655 6400,3640 6400,1130 4305,1130 4285,1150 4300,1165 4300,3085
GND on Bottom Layer "Top Layer-No Net" (hatched 90Degree grid 11.81 track 11.81, remove dead copper, pour order 1001): 4295,3090 5535,3090 5535,3680 5540,3685 6395,3685 6395,1135 6400,1130 6395,1135 4305,1135 4305,3085 4300,3090

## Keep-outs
Keep-Out Layer:
  lines w10: 4340,1175 6370,1175 6370,3655 4340,3655 4340,1175

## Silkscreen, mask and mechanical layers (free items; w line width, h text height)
Top Overlay:
  text "V1.0" at 5010,3395 h80
  text "RESET" at 6145,2650 h35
